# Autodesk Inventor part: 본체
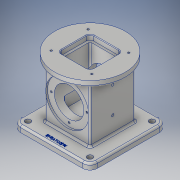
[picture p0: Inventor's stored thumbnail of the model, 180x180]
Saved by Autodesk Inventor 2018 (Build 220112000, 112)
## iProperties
Created: 2021-05
Part Number: 본체
Material: 알루미늄 6061
Document SubType Name: Modeling
Designer: 1class6
Density: 2.7 g/cm^3
Appearance: 알루미늄 - 평지
Mass: 1250.21 g
Surface Area: 897.912 cm^2
Volume: 463.042 cm^3
Author: 1class6
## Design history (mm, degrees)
sketch "스케치1"
  geometry: L1 (62.5, 62.5)-(-62.5, 62.5); L2 (-62.5, 62.5)-(-62.5, -62.5); L3 (-62.5, -62.5)-(62.5, -62.5); L4 (62.5, -62.5)-(62.5, 62.5); L5 (62.5, 62.5)-(-62.5, -62.5); L6 (-62.5, 62.5)-(62.5, -62.5); 1 further point
  constraints: 12 end point, 2 midpoint, 2 parallel, 1 horizontal, 1 perpendicular
  dimensions: "d0" = 125 distance between parallel lines of L2 L4; "d1" = 125 distance between parallel lines of L1 L3 (= d0)
extrude "돌출1" new body sketch "스케치1" distance "d2" = 10; taper "d3" = 0 deg
sketch "스케치2"
  geometry: L1 (-37, -37)-(37, -37); L2 (37, -37)-(37, 37); L3 (37, 37)-(-37, 37); L4 (-37, 37)-(-37, -37); L5 (-37, -37)-(37, 37); L6 (37, -37)-(-37, 37); 1 further point
  constraints: 12 end point, 2 midpoint, 2 parallel, 1 horizontal, 1 perpendicular
  dimensions: "d4" = 74 distance between parallel lines of L2 L4; "d5" = 74 distance between parallel lines of L1 L3 (= d4)
extrude "돌출2" join sketch "스케치2" distance "d6" = 88; taper "d7" = 0 deg
sketch "스케치3"
  geometry: C1 r 57.5 at (0, 0); 1 further point
  constraints: 1 centre point, 1 coincident
  dimensions: "d8" = 115 diameter of C1
extrude "돌출3" join sketch "스케치3" distance "d9" = 10; taper "d10" = 0 deg
sketch "스케치5"
  geometry: L1 (0, 0)-(0, 18); L2 (0, 18)-(24.826, 18); L3 (24.826, 18)-(28, 0); L4 (62.5, 0)-(-62.5, 0) reference; L5 (0, 0)-(28, 0)
  constraints: 8 end point, 1 collinear, 1 perpendicular, 1 point on line, 1 vertical
  dimensions: "d11" = 18 distance between parallel lines of L4 L2; "d12" = 80 deg angle of L4 L3; "d13" = 56 diameter of L3.end L1
revolve "회전1" sketch "스케치5" stored, may be unused: angle "d14" = 90 deg
sketch "스케치6"
  geometry: L1 (-25.5, -10)-(99.5, -10) reference; C1 r 24 at (37, 44); 2 further points
  constraints: 1 centre point, 1 midpoint, 1 vertical alignment
  dimensions: "d15" = 54 distance from line of C1.centre L1; "d16" = 48 diameter of C1
extrude "돌출4" cut sketch "스케치6" extent not by distance; stored distance "d17" = 0; taper "d18" = 0 deg
sketch "스케치7"
  geometry: C1 r 24 at (37, 44) reference; C2 r 35 at (37, 44); 1 further point
  constraints: 1 centre point, 1 coincident
  dimensions: "d19" = 70 diameter of C2
extrude "돌출5" cut sketch "스케치7" distance "d20" = 3; taper "d21" = 0 deg
sketch "스케치8"
  geometry: L1 (-26, -26)-(26, -26); L2 (26, -26)-(26, 26); L3 (26, 26)-(-26, 26); L4 (-26, 26)-(-26, -26); L5 (-26, -26)-(26, 26); L6 (26, -26)-(-26, 26); C1 r 57.5 at (0, 0) reference
  constraints: 12 end point, 2 midpoint, 2 parallel, 1 horizontal, 1 perpendicular
  dimensions: "d22" = 52 distance between parallel lines of L2 L4; "d23" = 52 distance between parallel lines of L1 L3 (= d22)
extrude "돌출6" cut sketch "스케치8" distance "d24" = 8; taper "d25" = 0 deg
sketch "스케치9"
  geometry: L1 (-22, -22)-(22, -22); L2 (22, -22)-(22, 22); L3 (22, 22)-(-22, 22); L4 (-22, 22)-(-22, -22); L5 (-22, -22)-(22, 22); L6 (22, -22)-(-22, 22); 1 further point
  constraints: 12 end point, 2 midpoint, 2 parallel, 1 horizontal, 1 perpendicular
  dimensions: "d26" = 44 distance between parallel lines of L2 L4; "d27" = 44 distance between parallel lines of L1 L3 (= d26)
extrude "돌출7" cut sketch "스케치9" distance "d28" = 74; taper "d29" = 0 deg
sketch "스케치11" dims "d30" = 58
  geometry: C1 r 35 at (0, 0) reference; 3 further points
  constraints: 1 coincident, 1 vertical alignment, 2 other
hole "구멍1" sketch "스케치11" at (0, 29) diameter "d31" = 3.242; stored, may be unused: countersink angle "d35" = 90 deg, drill point angle "d37" = 118 deg; dims "d32" = 8, "d33" = 4, "d34" = 2, "d36" = 10
sketch "스케치12"
  geometry: L1 (-33, -30)-(33, -30); L2 (33, -30)-(33, 30); L3 (33, 30)-(-33, 30); L4 (-33, 30)-(-33, -30); L5 (-33, -30)-(33, 30); L6 (33, -30)-(-33, 30); C1 r 57.5 at (0, 0) reference
  constraints: 12 end point, 2 midpoint, 2 parallel, 1 horizontal, 1 perpendicular
  dimensions: "d41" = 66 distance between parallel lines of L2 L4; "d42" = 60 distance between parallel lines of L1 L3
hole "구멍2" sketch "스케치12" at (33, 30), (33, -30), (-33, -30), (-33, 30) diameter "d43" = 3.242; stored, may be unused: countersink angle "d47" = 90 deg, drill point angle "d49" = 118 deg; dims "d44" = 8, "d45" = 4, "d46" = 2, "d48" = 10
fillet "모깎기1" dims "d50" = 12
sketch "스케치14"
  geometry: A1 r 12 centre (50.5, 50.5) between (62.5, 50.5) and (50.5, 62.5) reference; 1 further point
hole "구멍3" sketch "스케치14" at (50.5, 50.5) diameter "d51" = 9; stored, may be unused: countersink angle "d55" = 90 deg, drill point angle "d57" = 0 deg; dims "d52" = 8, "d53" = 4, "d54" = 2, "d56" = 10
sketch "스케치15"
  geometry: A1 r 12 centre (-50.5, 50.5) between (-50.5, 62.5) and (-62.5, 50.5) reference; A2 r 12 centre (-50.5, -50.5) between (-62.5, -50.5) and (-50.5, -62.5) reference; A3 r 12 centre (50.5, -50.5) between (50.5, -62.5) and (62.5, -50.5) reference; 3 further points
  constraints: 1 horizontal alignment, 1 other
hole "구멍4" sketch "스케치15" at (-50.5, -50.5), (50.5, -50.5), (-50.5, 50.5) diameter "d58" = 9; stored, may be unused: countersink angle "d62" = 90 deg, drill point angle "d64" = 0 deg; dims "d59" = 8, "d60" = 4, "d61" = 2, "d63" = 10
fillet "모깎기2" dims "d65" = 3
fillet "모깎기3" dims "d69" = 6
chamfer "모따기2" distance "d70" = 1; stored, may be unused: second distance "d71" = 2, angle "d72" = 45 deg
sketch "스케치17"
  geometry: L1 (-84.5, -13)-(16.5, -13) reference; 5 further points
  constraints: 2 midpoint, 2 vertical alignment
  dimensions: "d73" = 37 distance from line of point (-34, 24) L1; "d74" = 43 distance of point (-34, 67) point (-34, 24)
hole "구멍5" sketch "스케치17" at (-34, 24), (-34, 67) diameter "d75" = 4.134; stored, may be unused: countersink angle "d79" = 90 deg, drill point angle "d81" = 0 deg; dims "d76" = 30, "d77" = 4, "d78" = 2, "d80" = 30
sketch "스케치18"
  geometry: 2 further points
  constraints: 1 vertical alignment, 1 other
  dimensions: "d82" = 55 distance of point (0, 0) point (0, -55)
feature "엠보싱1" sketch "스케치18" dims "d0" = 125, "d1" = 125 (= d0), "d83" = 0.5, "d84" = 0
node "솔리드1"
mirror "미러1"
pattern_circular "원형 패턴1" dims angle "d39" = 360 deg
mirror "미러2"
